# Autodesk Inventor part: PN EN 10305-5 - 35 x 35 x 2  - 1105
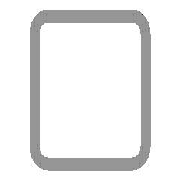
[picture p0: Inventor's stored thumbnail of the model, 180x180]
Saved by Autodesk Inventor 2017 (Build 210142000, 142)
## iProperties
Created: 2016-02
Part Number: PN EN 10305-5 - 35 x 35 x 2  - 1105
Material: Stal, miękka
Description: Rury stalowe do zastosowań precyzyjnych -  (Część 5: Rury kwadratowe, spawane, wymiarowane na zimno)
Document SubType Name: Modeling
Standard: PN
Designer: X
Standards Organization: PN
Language: pl-PL
Size Designation: 35 x 35 x 2
Categories: <MemberInstance><Categories><Category DisplayName="Kształtowniki konstrukcyjne" InternalName="089c4875-fa83-4c05-b084-43b9cc11f5ed" Mnemonic="GRDR"><CategoryPar
Stock Number: 35 x 35 x 2
Density: 7.85 g/cm^3
Appearance: Częściowo polerowana
IsCustomPart: 1
G_L: 1105,000 mm
G_W: 35,000 mm
G_H: 35,000 mm
_CCFamilyMember: 22
_CCFamilyDisplayName: PN EN 10305-5 (Rury kwadratowe, spawane, wymiarowane na zimno) - Rury stalowe do zastosowań precyzyjnych -  (Część 5: Rury kwadratowe, spawane, wymiarowane na z
_FrameMemberDoc: Frame Member File
_Version: 15.0.0
_GetPNFromCC: 1
Author: X
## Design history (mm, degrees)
node "Płaszczyzna początkowa"
node "Płaszczyzna końcowa"
sketch "Szkic"
  geometry: L1 (-17.5, -14.5)-(-17.5, 14.5); L2 (-14.5, 17.5)-(14.5, 17.5); L3 (17.5, 14.5)-(17.5, -14.5); L4 (14.5, -17.5)-(-14.5, -17.5); L5 (-14.5, 15.5)-(14.5, 15.5); L6 (15.5, 14.5)-(15.5, -14.5); L7 (14.5, -15.5)-(-14.5, -15.5); L8 (-15.5, -14.5)-(-15.5, 14.5); L9 (0, 25.37)-(0, -25.37) reference; L10 (-25.37, 0)-(25.37, 0) reference; A1 r 3 centre (-14.5, -14.5) between (-17.5, -14.5) and (-14.5, -17.5); A2 r 3 centre (-14.5, 14.5) between (-14.5, 17.5) and (-17.5, 14.5); A3 r 3 centre (14.5, 14.5) between (17.5, 14.5) and (14.5, 17.5); A4 r 3 centre (14.5, -14.5) between (14.5, -17.5) and (17.5, -14.5); A5 r 1 centre (-14.5, 14.5) between (-14.5, 15.5) and (-15.5, 14.5); A6 r 1 centre (14.5, 14.5) between (15.5, 14.5) and (14.5, 15.5); A7 r 1 centre (14.5, -14.5) between (14.5, -15.5) and (15.5, -14.5); A8 r 1 centre (-14.5, -14.5) between (-15.5, -14.5) and (-14.5, -15.5)
  constraints: 16 end point, 16 point on circle, 8 centre point, 8 tangent, 4 parallel, 3 equal radius, 2 perpendicular, 7 other
  dimensions: "d7" = 3 radius of A1 (= G_IR); "d10" = 35 distance between parallel lines of L2 L4 (= G_H); "d11" = 35 distance between parallel lines of L1 L3 (= G_W); "d12" = 2 distance between parallel lines of L3 L6 (= G_T); "d15" = 17.5 distance between parallel lines of L2 L10 (= 0.5 x d10); "d16" = 17.5 distance between parallel lines of L9 L3 (= 0.5 x d11)
extrude "Bryła" new body sketch "Szkic" stored distance "d3" = 1105 (= G_L); taper "d4" = 0 deg
node "Driven Length"
  sketch "Sketch3"
    geometry: L1 (0, 0)-(10, 0) reference
    constraints: 2 end point, 1 horizontal
  workplane "Work Plane3"
  sketch "Sketch4"
    geometry: L1 (-2, 35)-(12, 35) reference; L2 (-2, 1140)-(12, 1140) reference
    dimensions: "d18" = 1105 distance between parallel lines of L1 L2 (derived)
body "Solid1"
other parameters: "G_W" = 35 [user parameter; used in 1 equation term], "G_H" = 35 [user parameter; used in 1 equation term], "G_T" = 2 [user parameter; used in 1 equation term], "G_IR" = 3 [user parameter; used in 1 equation term], "G_L" = 1105 (= d18) [user parameter; used in 1 equation term], "G_OFFSET_START" = -35 [user parameter; used in 1 equation term], "G_OFFSET_END" = 0 [user parameter; used in 1 equation term], "d13" = 35 (= -G_OFFSET_START), "d17" = 90 deg
